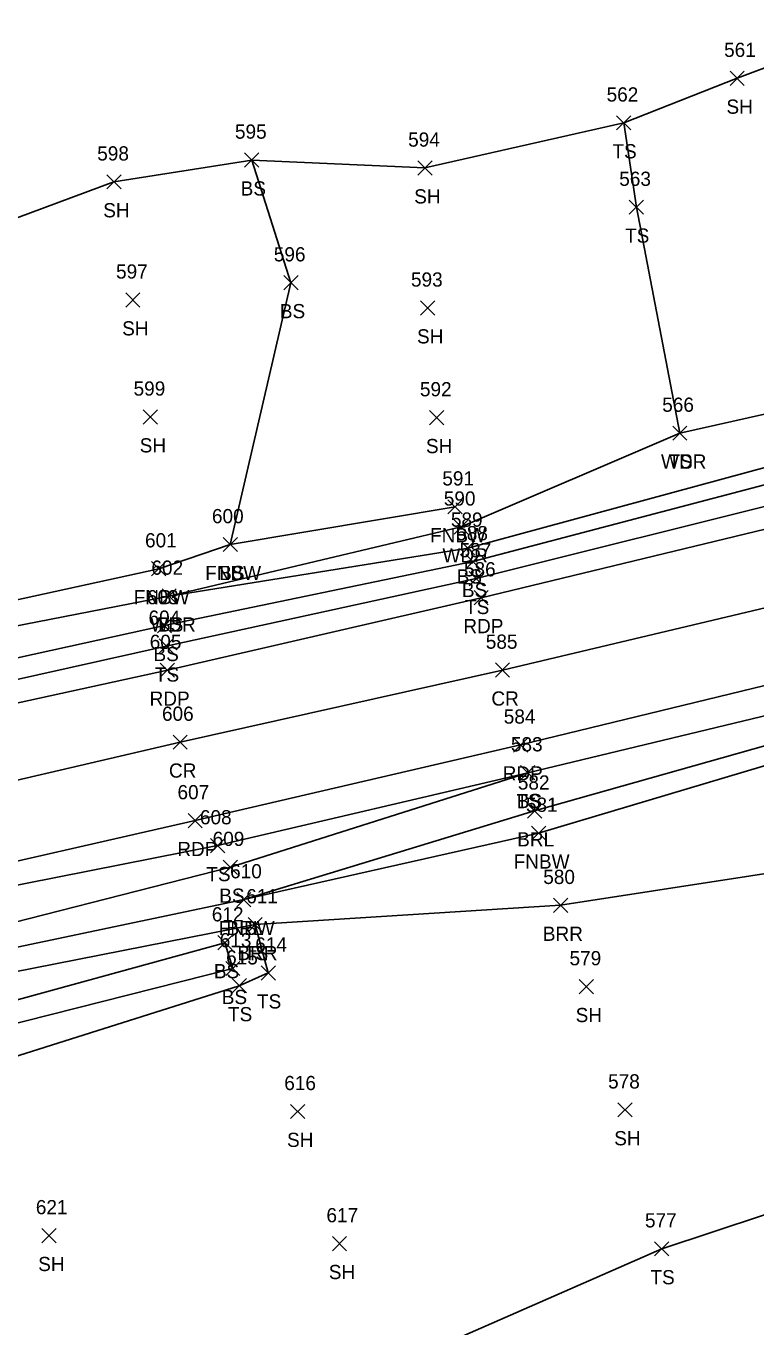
# Model space of a CAD drawing. Extents: x 1443590 to 1445966, y 578314 to 580556.
# Drawn here: x 1445735.4 to 1445838.2, y 579133.1 to 579316.2 of the extents above; entities that cross this region are included whole.
import ezdxf

# ---------------------------------------------------------------- set-up
doc = ezdxf.new("R2010")
doc.units = 0
for name, color, linetype in [('L_A', 7, 'Continuous'), ('L_I', 7, 'Continuous'), ('L_TIC', 7, 'Continuous'), ('LABL', 7, 'Continuous'), ('LAWA', 7, 'Continuous'), ('LELB', 7, 'Continuous'), ('LFNC', 7, 'Continuous'), ('LSOGP', 7, 'Continuous'), ('P_A', 7, 'Continuous'), ('P_I', 7, 'Continuous'), ('P_TIC', 7, 'Continuous'), ('PET', 7, 'Continuous'), ('PRC', 7, 'Continuous')]:
    doc.layers.add(name, color=color, linetype=linetype)

msp = doc.modelspace()

# ---------------------------------------------------------------- linework, layer by layer
at = {"layer": 'L_TIC'}
for points in [[(1445834.56, 579307.86), (1445836.56, 579309.86)], [(1445836.56, 579307.86), (1445834.56, 579309.86)], [(1445818.59, 579301.58), (1445820.59, 579303.58)], [(1445820.59, 579301.58), (1445818.59, 579303.58)], [(1445766.22, 579296.35), (1445768.22, 579298.35)], [(1445768.22, 579296.35), (1445766.22, 579298.35)], [(1445790.6, 579295.23), (1445792.6, 579297.23)], [(1445792.6, 579295.23), (1445790.6, 579297.23)], [(1445746.83, 579293.28), (1445748.83, 579295.28)], [(1445748.83, 579293.28), (1445746.83, 579295.28)], [(1445820.37, 579289.71), (1445822.37, 579291.71)], [(1445822.37, 579289.71), (1445820.37, 579291.71)], [(1445771.74, 579279.08), (1445773.74, 579281.08)], [(1445773.74, 579279.08), (1445771.74, 579281.08)], [(1445749.49, 579276.66), (1445751.49, 579278.66)], [(1445751.49, 579276.66), (1445749.49, 579278.66)], [(1445791, 579275.53), (1445793, 579277.53)], [(1445793, 579275.53), (1445791, 579277.53)], [(1445751.96, 579260.19), (1445753.96, 579262.19)], [(1445753.96, 579260.19), (1445751.96, 579262.19)], [(1445792.26, 579260.09), (1445794.26, 579262.09)], [(1445794.26, 579260.09), (1445792.26, 579262.09)], [(1445826.48, 579257.91), (1445828.48, 579259.91)], [(1445828.48, 579257.91), (1445826.48, 579259.91)], [(1445826.48, 579257.91), (1445828.48, 579259.91)], [(1445828.48, 579257.91), (1445826.48, 579259.91)], [(1445794.85, 579247.54), (1445796.85, 579249.54)], [(1445796.85, 579247.54), (1445794.85, 579249.54)], [(1445795.71, 579244.71), (1445797.71, 579246.71)], [(1445797.71, 579244.71), (1445795.71, 579246.71)], [(1445763.2, 579242.23), (1445765.2, 579244.23)], [(1445765.2, 579242.23), (1445763.2, 579244.23)], [(1445763.2, 579242.23), (1445765.2, 579244.23)], [(1445765.2, 579242.23), (1445763.2, 579244.23)], [(1445796.63, 579241.74), (1445798.63, 579243.74)], [(1445798.63, 579241.74), (1445796.63, 579243.74)], [(1445753.13, 579238.83), (1445755.13, 579240.83)], [(1445755.13, 579238.83), (1445753.13, 579240.83)], [(1445797.37, 579239.83), (1445799.37, 579241.83)], [(1445799.37, 579239.83), (1445797.37, 579241.83)], [(1445797.84, 579237.44), (1445799.84, 579239.44)], [(1445799.84, 579237.44), (1445797.84, 579239.44)], [(1445754.59, 579234.98), (1445756.59, 579236.98)], [(1445756.59, 579234.98), (1445754.59, 579236.98)], [(1445754.59, 579234.98), (1445756.59, 579236.98)], [(1445756.59, 579234.98), (1445754.59, 579236.98)], [(1445753.95, 579230.82), (1445755.95, 579232.82)], [(1445755.95, 579230.82), (1445753.95, 579232.82)], [(1445754.18, 579227.94), (1445756.18, 579229.94)], [(1445756.18, 579227.94), (1445754.18, 579229.94)], [(1445805.08, 579210.12), (1445807.08, 579212.12)], [(1445807.08, 579210.12), (1445805.08, 579212.12)], [(1445805.08, 579210.12), (1445807.08, 579212.12)], [(1445807.08, 579210.12), (1445805.08, 579212.12)], [(1445806.04, 579204.74), (1445808.04, 579206.74)], [(1445808.04, 579204.74), (1445806.04, 579206.74)], [(1445761.42, 579199.85), (1445763.42, 579201.85)], [(1445763.42, 579199.85), (1445761.42, 579201.85)], [(1445806.61, 579201.61), (1445808.61, 579203.61)], [(1445808.61, 579201.61), (1445806.61, 579203.61)], [(1445763.21, 579196.81), (1445765.21, 579198.81)], [(1445765.21, 579196.81), (1445763.21, 579198.81)], [(1445765.11, 579192.25), (1445767.11, 579194.25)], [(1445767.11, 579192.25), (1445765.11, 579194.25)], [(1445765.11, 579192.25), (1445767.11, 579194.25)], [(1445767.11, 579192.25), (1445765.11, 579194.25)], [(1445809.71, 579191.45), (1445811.71, 579193.45)], [(1445811.71, 579191.45), (1445809.71, 579193.45)], [(1445766.71, 579188.73), (1445768.71, 579190.73)], [(1445768.71, 579188.73), (1445766.71, 579190.73)], [(1445766.71, 579188.73), (1445768.71, 579190.73)], [(1445768.71, 579188.73), (1445766.71, 579190.73)], [(1445762.45, 579186.19), (1445764.45, 579188.19)], [(1445764.45, 579186.19), (1445762.45, 579188.19)], [(1445762.45, 579186.19), (1445764.45, 579188.19)], [(1445764.45, 579186.19), (1445762.45, 579188.19)], [(1445763.56, 579182.55), (1445765.56, 579184.55)], [(1445765.56, 579182.55), (1445763.56, 579184.55)], [(1445768.55, 579181.93), (1445770.55, 579183.93)], [(1445770.55, 579181.93), (1445768.55, 579183.93)], [(1445764.47, 579180.13), (1445766.47, 579182.13)], [(1445766.47, 579180.13), (1445764.47, 579182.13)], [(1445813.33, 579180.01), (1445815.33, 579182.01)], [(1445815.33, 579180.01), (1445813.33, 579182.01)], [(1445772.7, 579162.44), (1445774.7, 579164.44)], [(1445774.7, 579162.44), (1445772.7, 579164.44)], [(1445818.76, 579162.67), (1445820.76, 579164.67)], [(1445820.76, 579162.67), (1445818.76, 579164.67)], [(1445737.67, 579144.97), (1445739.67, 579146.97)], [(1445739.67, 579144.97), (1445737.67, 579146.97)], [(1445778.58, 579143.84), (1445780.58, 579145.84)], [(1445780.58, 579143.84), (1445778.58, 579145.84)], [(1445823.94, 579143.11), (1445825.94, 579145.11)], [(1445825.94, 579143.11), (1445823.94, 579145.11)]]:
    msp.add_lwpolyline(points, dxfattribs=at)
at = {"layer": 'LABL'}
for points in [[(1445906.55, 579212.65), (1445902.84, 579225.05), (1445898.01, 579226.74), (1445851.9, 579218.42), (1445807.04, 579205.74), (1445766.11, 579193.25)], [(1445906.55, 579212.65), (1445879.71, 579204.72), (1445850.58, 579198.62), (1445810.71, 579192.45), (1445767.71, 579189.73), (1445724.08, 579181.18), (1445680.91, 579170.42), (1445633.84, 579155.99), (1445592.6, 579145.22), (1445551.97, 579134.61), (1445508.87, 579124.99), (1445465.31, 579114.87), (1445423.98, 579104.34)]]:
    msp.add_lwpolyline(points, dxfattribs=at)
at = {"layer": 'LAWA'}
msp.add_lwpolyline([(1445940.22, 579284.43), (1445885.83, 579272.36), (1445844.44, 579262.69), (1445827.48, 579258.91), (1445796.71, 579245.71), (1445755.59, 579235.98), (1445712.93, 579227.65), (1445690.54, 579223.96), (1445678.14, 579218.71), (1445669.83, 579217.4), (1445660.64, 579215.29), (1445650.82, 579212.91), (1445620.88, 579206.25), (1445585.32, 579198.49), (1445581.88, 579199.68), (1445534.95, 579191.15), (1445499.12, 579184.35), (1445452.48, 579169.9), (1445413.76, 579163.53), (1445389.98, 579158.81), (1445383.55, 579156.95)], dxfattribs=at)
at = {"layer": 'LELB'}
for points in [[(1445819.59, 579302.58), (1445821.37, 579290.71), (1445827.48, 579258.91)], [(1445767.22, 579297.35), (1445772.74, 579280.08), (1445764.2, 579243.23)], [(1445941.93, 579277.61), (1445889.3, 579265.36), (1445843.98, 579255.27), (1445797.63, 579242.74), (1445755.59, 579235.98)], [(1445942.28, 579274.76), (1445889.96, 579263.07), (1445844.03, 579252.87), (1445798.37, 579240.83), (1445754.95, 579231.82), (1445713.51, 579222.75), (1445671.18, 579212.96), (1445621.87, 579202.82), (1445582.2, 579193.33), (1445537.64, 579181.65), (1445500.79, 579174.99), (1445454.59, 579163.7), (1445413.89, 579156.57), (1445390.87, 579153.03), (1445388.01, 579152.33), (1445386.99, 579153.05), (1445384.05, 579149.01)], [(1445942.54, 579272.88), (1445891.62, 579260.69), (1445844.68, 579249.92), (1445798.84, 579238.44), (1445755.18, 579228.94), (1445714.18, 579219.76), (1445671.32, 579209.34), (1445621.86, 579198.5), (1445582.62, 579189.65), (1445538.19, 579178.91), (1445501.35, 579171.14), (1445454.81, 579160.63), (1445415.54, 579151.91), (1445387.13, 579144.4), (1445381, 579142.46), (1445332.01, 579134.76), (1445286.79, 579125.14)], [(1445885.78, 579229.39), (1445850.36, 579221.75), (1445806.08, 579211.12), (1445764.21, 579197.81), (1445722.66, 579187.24), (1445678.57, 579179.16), (1445630.17, 579165.14), (1445590.01, 579156.78), (1445545.78, 579146.09), (1445506.67, 579139.71), (1445463.39, 579125.06), (1445422.67, 579116.07), (1445395.65, 579110.15), (1445393.02, 579109.29)], [(1445806.08, 579211.12), (1445762.42, 579200.85), (1445721.8, 579192.86), (1445676.81, 579183.17), (1445628.91, 579172.51), (1445588.96, 579161.55), (1445544.94, 579151.67), (1445505.74, 579144.31), (1445461.73, 579132.54), (1445420.98, 579122.48), (1445392.8, 579116.72), (1445384.72, 579116.17), (1445337.84, 579106.44), (1445294.36, 579095.47), (1445264.43, 579088.86), (1445254.07, 579086.81), (1445243.15, 579080.33), (1445227.05, 579067.57), (1445218.63, 579054.58), (1445214.55, 579043.43)], [(1445767.71, 579189.73), (1445769.55, 579182.93), (1445765.47, 579181.13), (1445730.83, 579170.18), (1445684, 579159.1), (1445636.58, 579144.74), (1445595.78, 579133.7), (1445555.1, 579121.04), (1445510.62, 579111.48), (1445467.9, 579100.48), (1445424.67, 579092.13), (1445397.59, 579082.57), (1445383.73, 579074.7), (1445374.6, 579053.01), (1445370.93, 579034.72)], [(1445763.45, 579187.19), (1445726.85, 579177.14), (1445682.27, 579166.7), (1445634.8, 579152.14), (1445594.22, 579140.59), (1445552.72, 579130.37), (1445509.46, 579119.23), (1445465.25, 579110.19), (1445423.33, 579100.85), (1445394.74, 579092.28), (1445387.84, 579092.34), (1445387.39, 579099.59), (1445390.91, 579104.48), (1445390.5, 579108.7), (1445390.05, 579112.49), (1445388.46, 579111.83), (1445389.06, 579108.23), (1445388.43, 579106.79), (1445384.9, 579102.1), (1445382.74, 579094.99), (1445374.47, 579077.54), (1445367.34, 579057.59), (1445362.91, 579033.07)], [(1445763.45, 579187.19), (1445764.56, 579183.55), (1445727.83, 579174.27), (1445682.59, 579163.41), (1445635.26, 579149.24), (1445594.61, 579136.52), (1445553.39, 579126.28), (1445509.79, 579116), (1445466.32, 579104.81), (1445423.92, 579095.99), (1445394.53, 579088.21), (1445383.79, 579087.03), (1445379.06, 579077.34), (1445369.46, 579055.39), (1445365.9, 579033.98)], [(1445893.37, 579165.51), (1445861.25, 579156.12), (1445824.94, 579144.11), (1445785.01, 579126.59), (1445747.93, 579100.23)]]:
    msp.add_lwpolyline(points, dxfattribs=at)
at = {"layer": 'LFNC'}
for points in [[(1445795.85, 579248.54), (1445764.2, 579243.23), (1445754.13, 579239.83), (1445711.84, 579230.59), (1445690.15, 579228.03), (1445678.15, 579223.24), (1445660.25, 579218.27), (1445650, 579215.14), (1445620.71, 579208.42), (1445581.88, 579199.68), (1445535.48, 579187.73), (1445499.96, 579180.85), (1445452.48, 579169.9)], [(1445902.84, 579225.05), (1445852.13, 579215.87), (1445807.61, 579202.61), (1445766.11, 579193.25), (1445723.45, 579184.3), (1445680.3, 579173.66), (1445630.64, 579161.81), (1445590.42, 579152.26), (1445545.94, 579141.53), (1445509.41, 579134.37)]]:
    msp.add_lwpolyline(points, dxfattribs=at)
at = {"layer": 'LSOGP'}
for points in [[(1445855.15, 579316.21), (1445835.56, 579308.86), (1445819.59, 579302.58), (1445791.6, 579296.23), (1445767.22, 579297.35), (1445747.83, 579294.28), (1445700.85, 579276.83)], [(1445785.01, 579126.59), (1445824.94, 579144.1), (1445861.25, 579156.12)]]:
    msp.add_lwpolyline(points, dxfattribs=at)
at = {"layer": 'P_TIC'}
for points in [[(1445798.52, 579234.75), (1445800.52, 579236.75)], [(1445800.52, 579234.75), (1445798.52, 579236.75)], [(1445754.35, 579224.54), (1445756.35, 579226.54)], [(1445756.35, 579224.54), (1445754.35, 579226.54)], [(1445801.53, 579224.56), (1445803.53, 579226.56)], [(1445803.53, 579224.56), (1445801.53, 579226.56)], [(1445756.14, 579214.42), (1445758.14, 579216.42)], [(1445758.14, 579214.42), (1445756.14, 579216.42)], [(1445804.07, 579214.02), (1445806.07, 579216.02)], [(1445806.07, 579214.02), (1445804.07, 579216.02)], [(1445758.26, 579203.38), (1445760.26, 579205.38)], [(1445760.26, 579203.38), (1445758.26, 579205.38)]]:
    msp.add_lwpolyline(points, dxfattribs=at)
at = {"layer": 'PET'}
for points in [[(1445943.14, 579270.25), (1445892.4, 579257.65), (1445845.31, 579246.81), (1445799.52, 579235.75), (1445755.35, 579225.54), (1445715.18, 579216.79), (1445671.87, 579207.04), (1445622.31, 579195.93), (1445583.17, 579187.01), (1445538.83, 579176.4), (1445501.67, 579168.43), (1445455.4, 579157.53)], [(1445949.39, 579249.16), (1445926.73, 579244.22), (1445898.7, 579237.56), (1445849.3, 579225.79), (1445805.07, 579215.02), (1445759.26, 579204.38), (1445720.95, 579195.67), (1445676.19, 579185.93), (1445628.6, 579174.84), (1445587.96, 579165.75), (1445544.25, 579155.66), (1445505.3, 579147.27), (1445460.87, 579137.08)]]:
    msp.add_lwpolyline(points, dxfattribs=at)
at = {"layer": 'PRC'}
msp.add_lwpolyline([(1445946.61, 579260.36), (1445895.63, 579247.77), (1445847, 579236.09), (1445802.53, 579225.56), (1445757.14, 579215.42), (1445718.47, 579206.39), (1445674.15, 579196.1), (1445625.6, 579185.05), (1445585.49, 579175.81), (1445541.72, 579165.83), (1445503.37, 579157.52), (1445457.64, 579146.91)], dxfattribs=at)

# ---------------------------------------------------------------- texts
at = {"layer": 'L_A'}
for s, p in [('SH', (1445834.05, 579303.86)), ('TS', (1445818, 579297.58)), ('BS', (1445765.66, 579292.35)), ('SH', (1445790.09, 579291.23)), ('SH', (1445746.32, 579289.28)), ('TS', (1445819.78, 579285.71)), ('BS', (1445771.18, 579275.08)), ('SH', (1445748.98, 579272.66)), ('SH', (1445790.49, 579271.53)), ('SH', (1445751.45, 579256.19)), ('SH', (1445791.75, 579256.09)), ('WDR', (1445824.84, 579253.91)), ('TS', (1445825.88, 579253.91)), ('FNBW', (1445792.32, 579243.54)), ('WDR', (1445794.07, 579240.71)), ('FNBW', (1445760.67, 579238.23)), ('BS', (1445762.64, 579238.23)), ('BS', (1445796.07, 579237.74)), ('FNBW', (1445750.6, 579234.83)), ('BS', (1445796.81, 579235.83)), ('TS', (1445797.25, 579233.44)), ('WDR', (1445752.95, 579230.98)), ('BS', (1445754.03, 579230.98)), ('BS', (1445753.39, 579226.82)), ('TS', (1445753.59, 579223.94)), ('TS', (1445804.49, 579206.12)), ('BS', (1445804.52, 579206.12)), ('BRL', (1445804.59, 579200.74)), ('FNBW', (1445804.09, 579197.61)), ('TS', (1445760.83, 579195.85)), ('BS', (1445762.65, 579192.81)), ('FNBW', (1445762.58, 579188.25)), ('BRL', (1445763.66, 579188.25)), ('BRR', (1445808.2, 579187.45)), ('BRR', (1445765.2, 579184.73)), ('TS', (1445766.12, 579184.73)), ('BS', (1445761.89, 579182.19)), ('BS', (1445761.89, 579182.19)), ('BS', (1445763, 579178.55)), ('TS', (1445767.96, 579177.93)), ('TS', (1445763.88, 579176.13)), ('SH', (1445812.82, 579176.01)), ('SH', (1445772.19, 579158.44)), ('SH', (1445818.25, 579158.67)), ('SH', (1445737.16, 579140.97)), ('SH', (1445778.07, 579139.84)), ('TS', (1445823.35, 579139.11))]:
    msp.add_text(s, height=2, dxfattribs=at).set_placement(p)
at = {"layer": 'L_I'}
for s, p in [('561', (1445833.72, 579311.86)), ('562', (1445817.18, 579305.58)), ('595', (1445764.86, 579300.35)), ('594', (1445789.24, 579299.23)), ('598', (1445745.47, 579297.28)), ('563', (1445818.96, 579293.71)), ('596', (1445770.33, 579283.08)), ('597', (1445748.12, 579280.66)), ('593', (1445789.64, 579279.53)), ('599', (1445750.59, 579264.19)), ('592', (1445790.9, 579264.09)), ('566', (1445825.01, 579261.91)), ('566', (1445825.01, 579261.91)), ('591', (1445794.05, 579251.54)), ('590', (1445794.26, 579248.71)), ('600', (1445761.62, 579246.23)), ('600', (1445761.62, 579246.23)), ('589', (1445795.26, 579245.74)), ('588', (1445796.01, 579243.83)), ('601', (1445752.2, 579242.83)), ('587', (1445796.48, 579241.44)), ('602', (1445753.1, 579238.98)), ('602', (1445753.1, 579238.98)), ('603', (1445752.46, 579234.82)), ('604', (1445752.69, 579231.94)), ('583', (1445803.71, 579214.12)), ('583', (1445803.71, 579214.12)), ('582', (1445804.68, 579208.74)), ('581', (1445805.82, 579205.61)), ('608', (1445759.93, 579203.85)), ('609', (1445761.72, 579200.81)), ('610', (1445764.18, 579196.25)), ('610', (1445764.18, 579196.25)), ('580', (1445808.26, 579195.45)), ('611', (1445766.44, 579192.73)), ('611', (1445766.44, 579192.73)), ('612', (1445761.6, 579190.19)), ('612', (1445761.6, 579190.19)), ('613', (1445762.72, 579186.55)), ('614', (1445767.71, 579185.93)), ('615', (1445763.62, 579184.13)), ('579', (1445811.96, 579184.01)), ('616', (1445771.8, 579166.44)), ('578', (1445817.39, 579166.67)), ('621', (1445736.83, 579148.97)), ('617', (1445777.74, 579147.84)), ('577', (1445822.58, 579147.11))]:
    msp.add_text(s, height=2, dxfattribs=at).set_placement(p)
at = {"layer": 'P_A'}
for s, p in [('RDP', (1445797.01, 579230.75)), ('RDP', (1445752.84, 579220.54)), ('CR', (1445800.96, 579220.56)), ('CR', (1445755.57, 579210.42)), ('RDP', (1445802.55, 579210.02)), ('RDP', (1445756.74, 579199.38))]:
    msp.add_text(s, height=2, dxfattribs=at).set_placement(p)
at = {"layer": 'P_I'}
for s, p in [('586', (1445797.1, 579238.75)), ('605', (1445752.86, 579228.54)), ('585', (1445800.17, 579228.56)), ('606', (1445754.59, 579218.42)), ('584', (1445802.7, 579218.02)), ('607', (1445756.77, 579207.38))]:
    msp.add_text(s, height=2, dxfattribs=at).set_placement(p)

doc.saveas('drawing.dxf')
